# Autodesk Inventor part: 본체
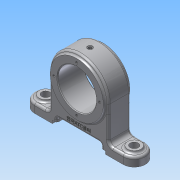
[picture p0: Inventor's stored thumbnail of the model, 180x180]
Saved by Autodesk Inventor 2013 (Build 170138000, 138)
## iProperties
Created: 2019-05
Part Number: 본체
Material: 알루미늄 6061
Document SubType Name: Modeling
Designer: Administrator
Density: 2.71 g/cm^3
Mass: 456.712 g
Surface Area: 318.708 cm^2
Volume: 168.528 cm^3
Author: Administrator
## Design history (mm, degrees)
sketch "스케치1"
  geometry: L1 (-40, 0)-(-40, -48); L2 (-75, -48)-(75, -48); L3 (75, -48)-(75, -60); L4 (75, -60)-(-75, -60); L5 (-75, -60)-(-75, -48); L6 (40, 0)-(40, -48); C1 r 26 at (0, 0); A1 r 40 centre (0, 0) between (40, 0) and (-40, 0); 2 further points
  constraints: 12 end point, 3 parallel, 2 centre point, 2 coincident, 2 point on circle, 2 point on line, 2 tangent, 1 horizontal, 1 midpoint, 1 perpendicular, 1 vertical, 1 vertical alignment
  dimensions: "d0" = 80 diameter of A1; "d2" = 150 distance of L3.end L4.end; "d3" = 60 distance from line of L4 point (0, 0); "d4" = 12 distance of L2.end L3.end; "d5" = 52 diameter of C1
extrude "돌출1" new body sketch "스케치1" stored distance "d6" = 30; taper "d7" = 0 deg
sketch "스케치2"
  geometry: C1 r 26 at (0, 0) reference; C2 r 36 at (0, 0); A1 r 40 centre (0, 0) between (40, 0) and (-40, 0) reference
  constraints: 1 centre point, 1 coincident
  dimensions: "d8" = 72 diameter of C2
extrude "돌출2" join sketch "스케치2" distance "d10" = 3; taper "d11" = 0 deg
sketch "스케치3"
  geometry: C1 r 26 at (0, 0) reference; C2 r 36 at (0, 0); A1 r 40 centre (0, 0) between (40, 0) and (-40, 0) reference
  constraints: 1 centre point, 1 coincident
  dimensions: "d12" = 72 diameter of C2
extrude "돌출3" join sketch "스케치3" distance "d13" = 3; taper "d14" = 0 deg
sketch "스케치4"
  geometry: C1 r 26 at (0, 0) reference; 1 further point
  constraints: 1 vertical alignment
  dimensions: "d15" = 31 distance of point (0, 31) C1.centre
hole "구멍1" sketch "스케치4" at (0, 31) diameter "d16" = 3.242; stored, may be unused: countersink angle "d20" = 90 deg, drill point angle "d22" = 118 deg; dims "d17" = 6, "d18" = 4, "d19" = 2, "d21" = 8
fillet "모깎기1" dims "d26" = 15
sketch "스케치5"
  geometry: C1 r 9 at (20, 15); A1 r 15 centre (20, 15) between (20, 0) and (20, 30) reference; 1 further point
  constraints: 1 centre point, 1 coincident
  dimensions: "d27" = 18 diameter of C1
extrude "돌출4" join sketch "스케치5" distance "d28" = 3; taper "d29" = 0 deg
sketch "스케치6"
  geometry: C1 r 9 at (0, 0) reference; C2 r 5.5 at (0, 0); 1 further point
  constraints: 1 centre point, 1 coincident
  dimensions: "d30" = 11 diameter of C2
extrude "돌출5" cut sketch "스케치6" stored distance "d31" = 3; taper "d32" = 0 deg
sketch "스케치7"
  geometry: C1 r 1.5 at (0, 26); 1 further point
  constraints: 2 vertical alignment, 1 centre point, 1 other
  dimensions: "d33" = 3 diameter of C1
extrude "돌출6" cut sketch "스케치7" stored distance "d34" = 3; taper "d35" = 0 deg
fillet "모깎기2" dims "d36" = 6
sketch "스케치8"
  geometry: L1 (-60, -60)-(60, -60) reference; L2 (-30, -50)-(30, -50); L3 (30, -50)-(30, -60); L4 (30, -60)-(-30, -60); L5 (-30, -60)-(-30, -50); L6 (-36, -56)-(36, -56); L7 (36, -56)-(36, -60); L8 (36, -60)-(-36, -60); L9 (-36, -60)-(-36, -56); C1 r 36 at (0, 0) reference; A1 r 40 centre (0, 0) between (40, 0) and (-40, 0) reference; 2 further points
  constraints: 16 end point, 4 parallel, 2 collinear, 2 horizontal, 2 midpoint, 2 perpendicular, 2 vertical alignment
  dimensions: "d37" = 60 distance of L3.end L4.end; "d39" = 72 distance of L7.end L8.end; "d40" = 10 distance of L2.end L3.end; "d41" = 4 distance of L6.end L7.end
extrude "돌출7" cut sketch "스케치8" stored distance "d42" = 3; taper "d43" = 0 deg
node "작업 평면1"
sketch "스케치9"
  geometry: C1 r 3.5 at (0, 0); 1 further point
  constraints: 1 centre point, 1 coincident
  dimensions: "d45" = 7 diameter of C1
extrude "돌출8" cut sketch "스케치9" distance "d46" = 1; taper "d47" = 0 deg
node "작업 평면5"
sketch "스케치10"
  geometry: C1 r 1 at (0, 0); 1 further point
  constraints: 1 centre point, 1 coincident
  dimensions: "d61" = 2 diameter of C1
extrude "돌출9" cut sketch "스케치10" stored distance "d62" = 1; taper "d63" = 0 deg
node "작업 평면6"
sketch "스케치11"
  geometry: 2 further points
  constraints: 1 coincident
hole "구멍3" sketch "스케치11" at (0, 0) diameter "d65" = 4.917; stored, may be unused: countersink angle "d69" = 90 deg, drill point angle "d71" = 118 deg; dims "d66" = 8, "d67" = 4, "d68" = 2, "d70" = 10
fillet "모깎기9" dims "d88" = 3
fillet "모깎기10" dims "d89" = 3
fillet "모깎기4" dims "d77" = 3
chamfer "모따기1" distance "d78" = 1; stored, may be unused: second distance "d79" = 2, angle "d80" = 45 deg
fillet "모깎기7" dims "d83" = 3
fillet "모깎기8" dims "d84" = 3
sketch "스케치14"
  geometry: L1 (-27, -50)-(27, -50) reference; A1 r 39 centre (0, 0) between (-37, -12.329) and (37, -12.329) reference; 1 further point
  constraints: 1 vertical alignment, 1 other
  dimensions: "d90" = 7 distance from line of point (0, -43) L1
feature "엠보싱2" sketch "스케치14" dims "d0" = 80, "d2" = 150, "d3" = 60, "d4" = 12, "d5" = 52, "d91" = 0.5, "d92" = 0
node "솔리드1"
pattern_circular "원형 패턴1" dims angle "d24" = 360 deg
mirror "대칭1"
mirror "대칭2"
other parameters: "d60" = 26
